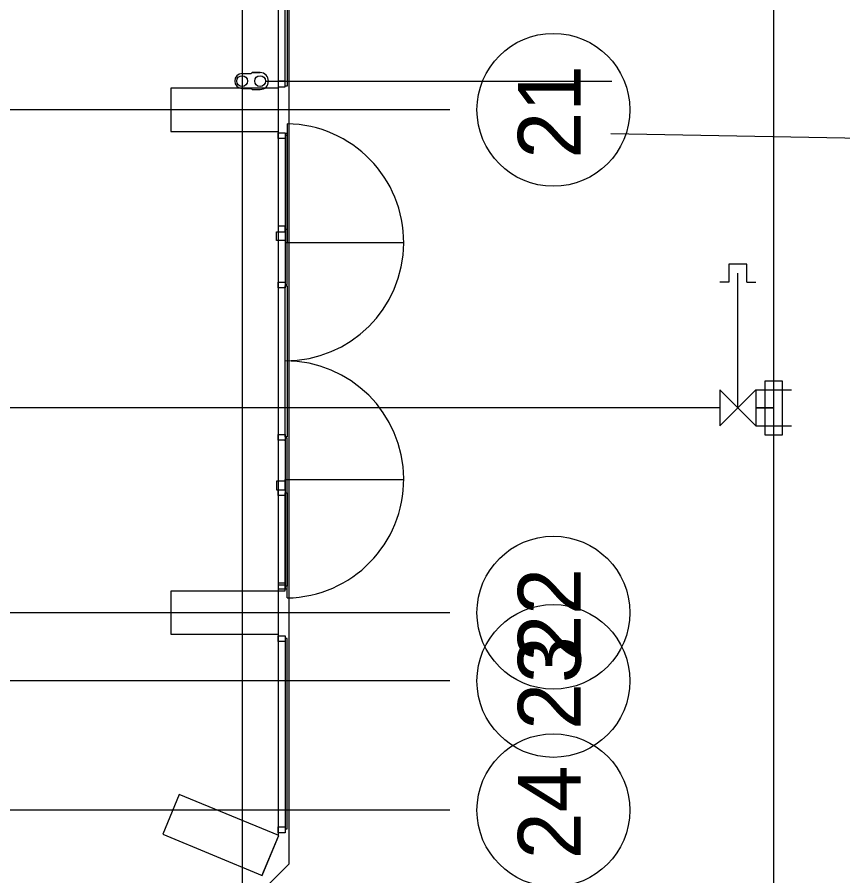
# Model space of a CAD drawing. Extents: x -264222 to -263592, y -1242345 to -1242048.
# Drawn here: x -263798.67 to -263787.18, y -1242227.54 to -1242215.59 of the extents above; entities that cross this region are included whole.
import ezdxf

# ---------------------------------------------------------------- set-up
doc = ezdxf.new("R2010")
doc.units = 0
doc.layers.add('HESCON_OSI_STAVBY_KFA', color=7, linetype='Continuous')
doc.layers.add('KFA_2D_SITUACIA_DSP', color=7, linetype='Continuous')

msp = doc.modelspace()

# ---------------------------------------------------------------- linework, layer by layer
at = {"layer": 'HESCON_OSI_STAVBY_KFA'}
for p, q in [((-263795.543, -1242083.237), (-263795.543, -1242246.707)), ((-263792.653, -1242216.882), (-263911.523, -1242216.882)), ((-263792.653, -1242216.882), (-263792.653, -1242216.882)), ((-263792.653, -1242223.882), (-263911.523, -1242223.882)), ((-263792.653, -1242223.882), (-263792.653, -1242223.882)), ((-263792.653, -1242224.832), (-263911.523, -1242224.832)), ((-263792.653, -1242224.832), (-263792.653, -1242224.832)), ((-263792.653, -1242226.632), (-263911.523, -1242226.632)), ((-263792.653, -1242226.632), (-263792.653, -1242226.632))]:
    msp.add_line(p, q, dxfattribs=at)
for centre in [(-263791.21, -1242216.882), (-263791.21, -1242223.882), (-263791.21, -1242224.832), (-263791.21, -1242226.632)]:
    msp.add_circle(centre, 1.064, dxfattribs=at)
at = {"layer": 'KFA_2D_SITUACIA_DSP'}
for p, q in [((-263788.143, -1242250.14), (-263788.143, -1242082.64)), ((-263795.043, -1242101.769), (-263795.043, -1242226.995)), ((-263794.943, -1242216.552), (-263794.943, -1242214.452)), ((-263794.918, -1242214.452), (-263794.918, -1242216.552)), ((-263795.543, -1242216.379), (-263795.418, -1242216.379)), ((-263795.418, -1242216.379), (-263795.404, -1242216.365)), ((-263795.293, -1242216.365), (-263795.404, -1242216.365)), ((-263795.404, -1242216.365), (-263795.293, -1242216.365)), ((-263795.218, -1242216.482), (-263790.395, -1242216.482)), ((-263794.943, -1242216.482), (-263795.043, -1242216.482)), ((-263795.043, -1242216.482), (-263795.043, -1242216.562)), ((-263794.943, -1242216.522), (-263794.943, -1242216.482)), ((-263795.038, -1242216.582), (-263796.538, -1242216.582)), ((-263796.538, -1242216.582), (-263796.538, -1242217.182)), ((-263795.543, -1242216.585), (-263795.418, -1242216.585)), ((-263795.418, -1242216.585), (-263795.404, -1242216.599)), ((-263795.404, -1242216.599), (-263795.293, -1242216.599)), ((-263795.043, -1242216.562), (-263794.943, -1242216.562)), ((-263795.038, -1242217.182), (-263795.038, -1242216.582)), ((-263794.943, -1242216.562), (-263794.943, -1242216.522)), ((-263794.918, -1242216.552), (-263794.943, -1242216.552)), ((-263794.918, -1242217.077), (-263794.918, -1242218.727)), ((-263796.538, -1242217.182), (-263795.038, -1242217.182)), ((-263795.043, -1242217.282), (-263795.043, -1242217.202)), ((-263795.043, -1242217.202), (-263794.943, -1242217.202)), ((-263795.043, -1242217.282), (-263795.043, -1242217.202)), ((-263795.043, -1242217.202), (-263794.943, -1242217.202)), ((-263794.943, -1242217.202), (-263794.943, -1242217.242)), ((-263794.943, -1242217.202), (-263794.943, -1242217.242)), ((-263794.918, -1242217.212), (-263794.943, -1242217.212)), ((-263794.943, -1242217.212), (-263794.943, -1242219.312)), ((-263794.918, -1242219.312), (-263794.918, -1242217.212)), ((-263781.818, -1242217.375), (-263790.409, -1242217.218)), ((-263794.943, -1242217.282), (-263795.043, -1242217.282)), ((-263794.943, -1242217.282), (-263795.043, -1242217.282)), ((-263794.943, -1242217.242), (-263794.943, -1242217.282)), ((-263794.918, -1242217.242), (-263794.943, -1242217.242)), ((-263794.943, -1242217.242), (-263794.943, -1242218.542)), ((-263794.943, -1242217.242), (-263794.943, -1242217.282)), ((-263794.918, -1242218.542), (-263794.918, -1242217.242)), ((-263794.943, -1242218.502), (-263795.043, -1242218.502)), ((-263795.043, -1242218.502), (-263795.043, -1242218.582)), ((-263794.943, -1242218.542), (-263794.943, -1242218.502)), ((-263795.063, -1242218.702), (-263795.063, -1242218.582)), ((-263795.063, -1242218.582), (-263794.943, -1242218.582)), ((-263795.043, -1242218.582), (-263794.943, -1242218.582)), ((-263794.943, -1242218.542), (-263794.918, -1242218.542)), ((-263794.943, -1242218.582), (-263794.943, -1242218.542)), ((-263794.943, -1242218.582), (-263794.943, -1242218.702)), ((-263794.943, -1242218.702), (-263795.063, -1242218.702)), ((-263794.943, -1242218.702), (-263794.943, -1242218.727)), ((-263794.943, -1242218.727), (-263793.293, -1242218.727)), ((-263788.768, -1242219.032), (-263788.768, -1242219.282)), ((-263788.518, -1242219.032), (-263788.768, -1242219.032)), ((-263788.518, -1242219.282), (-263788.518, -1242219.032)), ((-263788.643, -1242221.032), (-263788.643, -1242219.157)), ((-263795.043, -1242219.362), (-263795.043, -1242219.282)), ((-263795.043, -1242219.282), (-263794.943, -1242219.282)), ((-263794.943, -1242219.362), (-263795.043, -1242219.362)), ((-263794.943, -1242219.282), (-263794.943, -1242219.322)), ((-263794.943, -1242219.312), (-263794.918, -1242219.312)), ((-263794.943, -1242219.322), (-263794.943, -1242219.362)), ((-263794.943, -1242221.432), (-263794.943, -1242219.332)), ((-263794.943, -1242219.332), (-263794.918, -1242219.332)), ((-263794.918, -1242219.332), (-263794.918, -1242221.432)), ((-263788.768, -1242219.282), (-263788.893, -1242219.282)), ((-263788.518, -1242219.282), (-263788.393, -1242219.282)), ((-263788.268, -1242220.657), (-263788.268, -1242221.407)), ((-263788.018, -1242220.657), (-263788.268, -1242220.657)), ((-263788.018, -1242221.407), (-263788.018, -1242220.657)), ((-263788.893, -1242220.782), (-263788.893, -1242221.282)), ((-263788.393, -1242221.282), (-263788.893, -1242220.782)), ((-263788.893, -1242221.282), (-263788.393, -1242220.782)), ((-263788.393, -1242220.782), (-263788.393, -1242221.282)), ((-263788.393, -1242220.782), (-263787.893, -1242220.782)), ((-263788.893, -1242221.032), (-263800.593, -1242221.032)), ((-263788.143, -1242221.032), (-263788.393, -1242221.032)), ((-263788.393, -1242221.032), (-263788.143, -1242221.032)), ((-263788.393, -1242221.282), (-263787.893, -1242221.282)), ((-263795.043, -1242221.482), (-263795.043, -1242221.402)), ((-263795.043, -1242221.402), (-263794.943, -1242221.402)), ((-263794.943, -1242221.402), (-263794.943, -1242221.492)), ((-263788.268, -1242221.407), (-263788.018, -1242221.407)), ((-263794.943, -1242221.482), (-263795.043, -1242221.482)), ((-263794.918, -1242221.432), (-263794.943, -1242221.432)), ((-263794.918, -1242221.452), (-263794.943, -1242221.452)), ((-263794.943, -1242221.452), (-263794.943, -1242223.552)), ((-263794.943, -1242221.492), (-263794.943, -1242221.482)), ((-263794.918, -1242223.552), (-263794.918, -1242221.452)), ((-263794.943, -1242222.052), (-263795.063, -1242222.052)), ((-263795.063, -1242222.052), (-263795.063, -1242222.172)), ((-263794.943, -1242222.052), (-263794.943, -1242222.027)), ((-263794.943, -1242222.027), (-263793.293, -1242222.027)), ((-263794.943, -1242222.172), (-263794.943, -1242222.052)), ((-263794.918, -1242223.677), (-263794.918, -1242222.027)), ((-263795.063, -1242222.172), (-263794.943, -1242222.172)), ((-263795.043, -1242222.252), (-263795.043, -1242222.172)), ((-263795.043, -1242222.172), (-263794.943, -1242222.172)), ((-263794.943, -1242222.172), (-263794.943, -1242222.212)), ((-263794.943, -1242223.512), (-263794.943, -1242222.212)), ((-263794.943, -1242222.212), (-263794.918, -1242222.212)), ((-263794.943, -1242222.212), (-263794.943, -1242222.252)), ((-263794.918, -1242222.212), (-263794.918, -1242223.512)), ((-263794.943, -1242222.252), (-263795.043, -1242222.252)), ((-263794.943, -1242223.472), (-263795.043, -1242223.472)), ((-263795.043, -1242223.472), (-263795.043, -1242223.552)), ((-263794.943, -1242223.497), (-263795.043, -1242223.497)), ((-263795.043, -1242223.497), (-263795.043, -1242223.577)), ((-263795.043, -1242223.552), (-263794.943, -1242223.552)), ((-263794.943, -1242223.512), (-263794.943, -1242223.472)), ((-263794.943, -1242223.537), (-263794.943, -1242223.497)), ((-263794.918, -1242223.512), (-263794.943, -1242223.512)), ((-263794.943, -1242223.552), (-263794.943, -1242223.512)), ((-263794.943, -1242223.577), (-263794.943, -1242223.537)), ((-263794.943, -1242223.552), (-263794.918, -1242223.552)), ((-263795.038, -1242223.582), (-263796.538, -1242223.582)), ((-263796.538, -1242223.582), (-263796.538, -1242224.182)), ((-263795.043, -1242223.577), (-263794.943, -1242223.577)), ((-263795.038, -1242224.182), (-263795.038, -1242223.582)), ((-263796.538, -1242224.182), (-263795.038, -1242224.182)), ((-263795.043, -1242224.282), (-263795.043, -1242224.202)), ((-263795.043, -1242224.202), (-263794.943, -1242224.202)), ((-263794.943, -1242224.202), (-263794.943, -1242224.242)), ((-263794.918, -1242224.242), (-263794.943, -1242224.242)), ((-263794.943, -1242224.242), (-263794.943, -1242226.892)), ((-263794.943, -1242224.242), (-263794.943, -1242224.282)), ((-263794.918, -1242226.892), (-263794.918, -1242224.242)), ((-263794.943, -1242224.282), (-263795.043, -1242224.282)), ((-263796.418, -1242226.411), (-263796.648, -1242226.966)), ((-263795.032, -1242226.985), (-263796.418, -1242226.411)), ((-263795.043, -1242226.945), (-263795.043, -1242226.865)), ((-263795.043, -1242226.865), (-263794.943, -1242226.865)), ((-263794.943, -1242226.865), (-263794.943, -1242226.905)), ((-263794.943, -1242226.892), (-263794.918, -1242226.892)), ((-263794.943, -1242226.905), (-263794.943, -1242226.945)), ((-263796.648, -1242226.966), (-263795.262, -1242227.54)), ((-263795.043, -1242226.995), (-263795.272, -1242227.55)), ((-263795.262, -1242227.54), (-263795.032, -1242226.985)), ((-263794.943, -1242226.945), (-263795.043, -1242226.945))]:
    msp.add_line(p, q, dxfattribs=at)
msp.add_lwpolyline([(-263794.893, -1242227.382), (-263808.968, -1242241.457), (-263894.968, -1242241.457), (-263909.043, -1242227.382), (-263909.043, -1242196.333), (-263914.143, -1242196.333), (-263914.143, -1242132.433), (-263909.043, -1242132.433), (-263909.043, -1242101.382), (-263894.968, -1242087.307), (-263808.968, -1242087.307), (-263794.893, -1242101.382), (-263794.893, -1242227.382)], dxfattribs=at)
for centre in [(-263795.543, -1242216.482), (-263795.293, -1242216.482)]:
    msp.add_circle(centre, 0.075, dxfattribs=at)
for centre, radius, start, end in [((-263795.543, -1242216.482), 0.103, 90, 270), ((-263795.293, -1242216.482), 0.117, 270, 90), ((-263794.943, -1242218.727), 1.65, 270, 89.1318), ((-263794.943, -1242222.027), 1.65, 270.8682, 90)]:
    msp.add_arc(centre, radius, start, end, dxfattribs=at)

# ---------------------------------------------------------------- texts
at = {"layer": 'HESCON_OSI_STAVBY_KFA'}
for s, p in [('21', (-263790.829, -1242217.562)), ('22', (-263790.829, -1242224.562)), ('23', (-263790.829, -1242225.512)), ('24', (-263790.829, -1242227.312))]:
    msp.add_text(s, height=0.875, rotation=90, dxfattribs=at).set_placement(p)

doc.saveas('drawing.dxf')
